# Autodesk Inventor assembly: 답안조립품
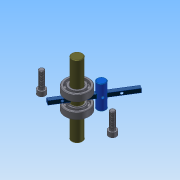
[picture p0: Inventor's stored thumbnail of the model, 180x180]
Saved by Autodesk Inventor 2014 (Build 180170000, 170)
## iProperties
Created: 2015-06
Part Number: 답안조립품
Document SubType Name: Assembly
Designer: Administrator
Author: Administrator
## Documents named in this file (9)
- C:\Documents and Settings\Administrator\바탕 화면\450631V1003\답안조립품.iam
- C:\Documents and Settings\Administrator\바탕 화면\450631V1003\본체.ipt
- C:\Documents and Settings\Administrator\바탕 화면\450631V1003\덮개.ipt
- C:\Documents and Settings\Administrator\바탕 화면\450631V1003\베어링62_22.ipt
- C:\Documents and Settings\Administrator\바탕 화면\450631V1003\축.ipt
- C:\Documents and Settings\Administrator\바탕 화면\450631V1003\멈춤링.ipt
- C:\Documents and Settings\Administrator\바탕 화면\450631V1003\M10x35.ipt
- C:\Documents and Settings\Administrator\바탕 화면\450631V1003\슬라이더.ipt
- C:\Documents and Settings\Administrator\바탕 화면\450631V1003\슬라이더2.ipt
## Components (6 placed, 3 different names)
1. KS B 1336 22 x 1.2:1
2. KS B 1336 22 x 1.2:2
3. KS B 1003 - 미터 M 10 x 35:1
4. KS B 1003 - 미터 M 10 x 35:2
5. KS B 2023 62/22 - 22 x 50 x 14:2
6. KS B 2023 62/22 - 22 x 50 x 14:3
